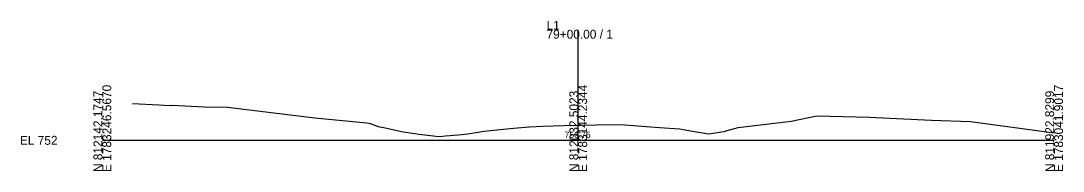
# Model space of a CAD drawing. Extents: x 5574 to 10203, y -10 to 9546.
# Drawn here: x 8574.3 to 8902.8, y 6990.3 to 7037.6 of the extents above; entities that cross this region are included whole.
import ezdxf

# ---------------------------------------------------------------- set-up
doc = ezdxf.new("R2010")
doc.units = 0
for name, color, linetype in [('Exist Cross Section Cell', 7, 'Continuous'), ('Exist XS Center Line Elevation Label', 7, 'Continuous'), ('Exist XS Ground Line', 7, 'Continuous')]:
    doc.layers.add(name, color=color, linetype=linetype)

msp = doc.modelspace()

# ---------------------------------------------------------------- linework, layer by layer
at = {"layer": 'Exist Cross Section Cell'}
for p, q in [((8750, 7000), (8750, 7034.79)), ((8600, 7000), (8750, 7000)), ((8750, 7000), (8900, 7000))]:
    msp.add_line(p, q, dxfattribs=at)
at = {"layer": 'Exist XS Ground Line'}
for p, q in [((8609.48, 7011.6), (8617.85, 7011.16)), ((8617.85, 7011.16), (8621.43, 7011.01)), ((8621.43, 7011.01), (8621.82, 7011.04)), ((8621.82, 7011.04), (8632.15, 7010.51)), ((8632.15, 7010.51), (8639.44, 7010.48)), ((8639.44, 7010.48), (8666.96, 7007.12)), ((8817.1, 7006.05), (8825.24, 7007.71)), ((8825.24, 7007.71), (8841.73, 7007.26)), ((8666.96, 7007.12), (8683.32, 7005.52)), ((8683.32, 7005.52), (8684.38, 7005.28)), ((8684.38, 7005.28), (8686.97, 7004.38)), ((8686.97, 7004.38), (8689.66, 7003.85)), ((8734.67, 7004.24), (8736.71, 7004.35)), ((8736.71, 7004.35), (8738.69, 7004.46)), ((8738.69, 7004.46), (8745.31, 7004.64)), ((8745.31, 7004.64), (8750, 7004.76)), ((8750, 7004.76), (8750.73, 7004.78)), ((8750.73, 7004.78), (8755.75, 7004.84)), ((8755.75, 7004.84), (8762.27, 7004.93)), ((8762.27, 7004.93), (8764.57, 7004.84)), ((8764.57, 7004.84), (8766.15, 7004.78)), ((8766.15, 7004.78), (8772.76, 7004.29)), ((8800.36, 7004.02), (8817.1, 7006.05)), ((8841.73, 7007.26), (8861.34, 7006.38)), ((8861.34, 7006.38), (8873.62, 7005.92)), ((8873.62, 7005.92), (8900, 7002.33)), ((8689.66, 7003.85), (8693.83, 7002.92)), ((8693.83, 7002.92), (8694.79, 7002.68)), ((8694.79, 7002.68), (8695.7, 7002.6)), ((8695.7, 7002.6), (8699.75, 7001.89)), ((8699.75, 7001.89), (8701.65, 7001.71)), ((8701.65, 7001.71), (8704.31, 7001.43)), ((8704.31, 7001.43), (8706.04, 7001.23)), ((8706.04, 7001.23), (8707.25, 7001.34)), ((8707.25, 7001.34), (8708.2, 7001.45)), ((8708.2, 7001.45), (8712.13, 7001.78)), ((8712.13, 7001.78), (8715.18, 7002.06)), ((8715.18, 7002.06), (8720.29, 7002.91)), ((8720.29, 7002.91), (8729.6, 7003.8)), ((8729.6, 7003.8), (8734.67, 7004.24)), ((8772.76, 7004.29), (8775.6, 7004.08)), ((8775.6, 7004.08), (8782.06, 7003.57)), ((8782.06, 7003.57), (8783.02, 7003.38)), ((8783.02, 7003.38), (8786.68, 7002.81)), ((8786.68, 7002.81), (8790.46, 7002.18)), ((8790.46, 7002.18), (8791.24, 7002.07)), ((8791.24, 7002.07), (8795.03, 7002.64)), ((8795.03, 7002.64), (8796.09, 7002.79)), ((8796.09, 7002.79), (8796.98, 7003.05)), ((8796.98, 7003.05), (8800.36, 7004.02))]:
    msp.add_line(p, q, dxfattribs=at)

# ---------------------------------------------------------------- texts
at = {"layer": 'Exist Cross Section Cell'}
for s, p in [('L1', (8740, 7034.79)), ('79+00.00 / 1', (8740, 7031.99)), ('EL 752', (8574, 6998.6))]:
    msp.add_text(s, height=2.8, dxfattribs=at).set_placement(p)
for s, p in [('N 812142.1747', (8600, 6990)), ('E 1783246.5670', (8602.8, 6990)), ('N 812032.5023', (8750, 6990)), ('E 1783144.2344', (8752.8, 6990)), ('N 811922.8299', (8900, 6990)), ('E 1783041.9017', (8902.8, 6990))]:
    msp.add_text(s, height=2.8, rotation=90, dxfattribs=at).set_placement(p)
at = {"layer": 'Exist XS Center Line Elevation Label'}
msp.add_text('756.76', height=2, dxfattribs=at).set_placement((8745.73, 7000.76))

doc.saveas('drawing.dxf')
